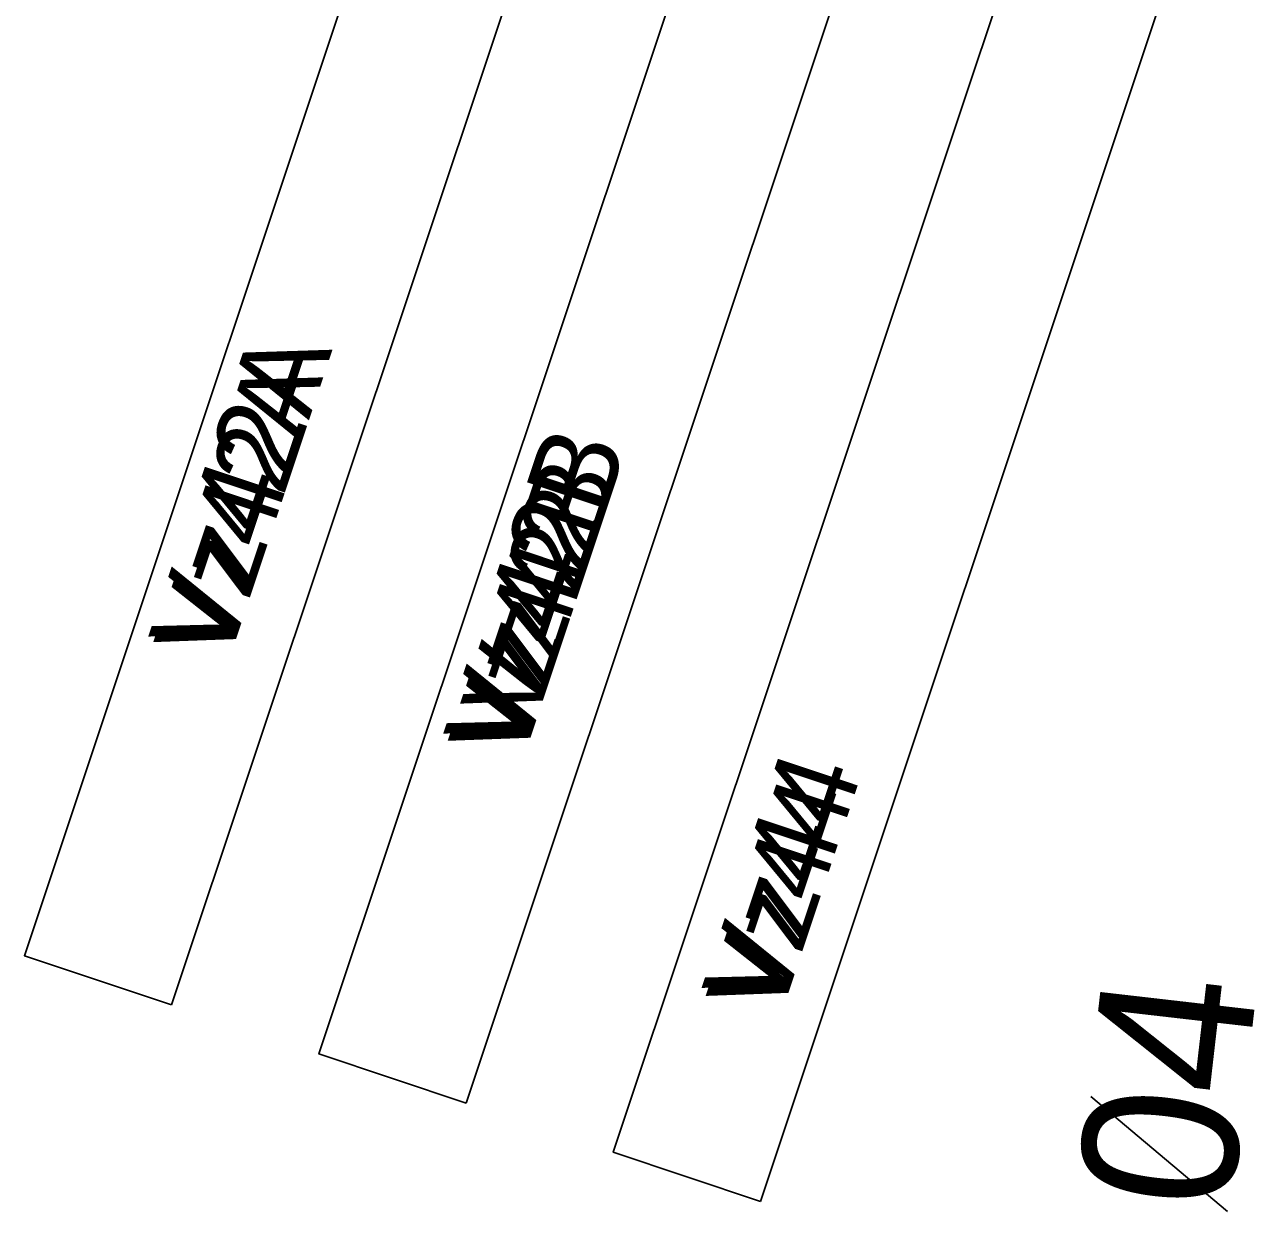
# Model space of a CAD drawing. Extents: x 647787 to 668496, y 640478 to 654412.
# Drawn here: x 662719.56 to 662766.75, y 647156.23 to 647202.12 of the extents above; entities that cross this region are included whole.
import ezdxf

# ---------------------------------------------------------------- set-up
doc = ezdxf.new("R2010")
doc.units = 0
for name, color, linetype in [('Default', 7, 'Continuous'), ('TEMP_DETECTION ZONE_Stage 2', 7, 'Continuous'), ('TEMP_DETECTION ZONE_STAGE 3', 7, 'Continuous'), ('TEMP_DETECTION_ZONE_STAGE 4', 7, 'Continuous'), ('TEMP_DETECTION_ZONE_STAGE 5', 7, 'Continuous'), ('TEMP_SIGNAL_POLES_STAGE 1B', 7, 'Continuous')]:
    doc.layers.add(name, color=color, linetype=linetype)

msp = doc.modelspace()

# ---------------------------------------------------------------- linework, layer by layer
at = {"layer": 'Default'}
msp.add_line((662760.805, 647160.681), (662766.087, 647156.225), dxfattribs=at)
at = {"layer": 'TEMP_DETECTION ZONE_Stage 2'}
for points in [[(662736.64, 647160.418), (662730.949, 647162.318), (662746.777, 647209.746), (662752.468, 647207.847)], [(662748.023, 647156.62), (662742.332, 647158.519), (662758.16, 647205.948), (662763.851, 647204.048)]]:
    msp.add_lwpolyline(points, close=True, dxfattribs=at)
at = {"layer": 'TEMP_DETECTION ZONE_STAGE 3'}
for points in [[(662725.249, 647164.22), (662719.558, 647166.119), (662735.385, 647213.548), (662741.077, 647211.648)], [(662736.64, 647160.418), (662730.949, 647162.318), (662746.777, 647209.746), (662752.468, 647207.847)], [(662748.023, 647156.62), (662742.332, 647158.519), (662758.16, 647205.948), (662763.851, 647204.048)]]:
    msp.add_lwpolyline(points, close=True, dxfattribs=at)
at = {"layer": 'TEMP_DETECTION_ZONE_STAGE 4'}
for points in [[(662725.249, 647164.22), (662719.558, 647166.119), (662735.385, 647213.548), (662741.077, 647211.648)], [(662736.64, 647160.418), (662730.949, 647162.318), (662746.777, 647209.746), (662752.468, 647207.847)], [(662748.023, 647156.62), (662742.332, 647158.519), (662758.16, 647205.948), (662763.851, 647204.048)]]:
    msp.add_lwpolyline(points, close=True, dxfattribs=at)
at = {"layer": 'TEMP_DETECTION_ZONE_STAGE 5'}
for points in [[(662725.249, 647164.22), (662719.558, 647166.119), (662735.385, 647213.548), (662741.077, 647211.648)], [(662736.64, 647160.418), (662730.949, 647162.318), (662746.777, 647209.746), (662752.468, 647207.847)], [(662748.023, 647156.62), (662742.332, 647158.519), (662758.16, 647205.948), (662763.851, 647204.048)]]:
    msp.add_lwpolyline(points, close=True, dxfattribs=at)
at = {"layer": 'TEMP_SIGNAL_POLES_STAGE 1B'}
for points in [[(662725.249, 647164.22), (662719.558, 647166.119), (662735.385, 647213.548), (662741.077, 647211.648)], [(662736.64, 647160.418), (662730.949, 647162.318), (662746.777, 647209.746), (662752.468, 647207.847)], [(662748.023, 647156.62), (662742.332, 647158.519), (662758.16, 647205.948), (662763.851, 647204.048)]]:
    msp.add_lwpolyline(points, close=True, dxfattribs=at)

# ---------------------------------------------------------------- texts
at = {"layer": 'Default'}
msp.add_text('04', height=6, rotation=83.4389, dxfattribs=at).set_placement((662766.224, 647156.168))
at = {"layer": 'TEMP_DETECTION ZONE_Stage 2'}
for s, p in [('Vz42', (662739.246, 647174.897)), ('Vz44', (662748.745, 647163.596))]:
    msp.add_text(s, height=3, rotation=71.5452, dxfattribs=at).set_placement(p)
at = {"layer": 'TEMP_DETECTION ZONE_STAGE 3'}
for s, p in [('Vz42A', (662727.379, 647177.275)), ('Vz42B', (662738.766, 647173.46)), ('Vz44', (662748.745, 647163.596))]:
    msp.add_text(s, height=3, rotation=71.5452, dxfattribs=at).set_placement(p)
at = {"layer": 'TEMP_DETECTION_ZONE_STAGE 4'}
for s, p in [('Vz42A', (662727.379, 647177.275)), ('Vz42B', (662738.766, 647173.46)), ('Vz44', (662748.745, 647163.596))]:
    msp.add_text(s, height=3, rotation=71.5452, dxfattribs=at).set_placement(p)
at = {"layer": 'TEMP_DETECTION_ZONE_STAGE 5'}
for s, p in [('Vz42A', (662727.379, 647177.275)), ('Vz42B', (662738.766, 647173.46)), ('Vz44', (662748.745, 647163.596))]:
    msp.add_text(s, height=3, rotation=71.5452, dxfattribs=at).set_placement(p)
at = {"layer": 'TEMP_SIGNAL_POLES_STAGE 1B'}
for s, p in [('Vz42A', (662727.424, 647177.409)), ('Vz42B', (662738.832, 647173.656)), ('Vz44', (662748.821, 647163.824))]:
    msp.add_text(s, height=3.25, rotation=71.5452, dxfattribs=at).set_placement(p)

doc.saveas('drawing.dxf')
